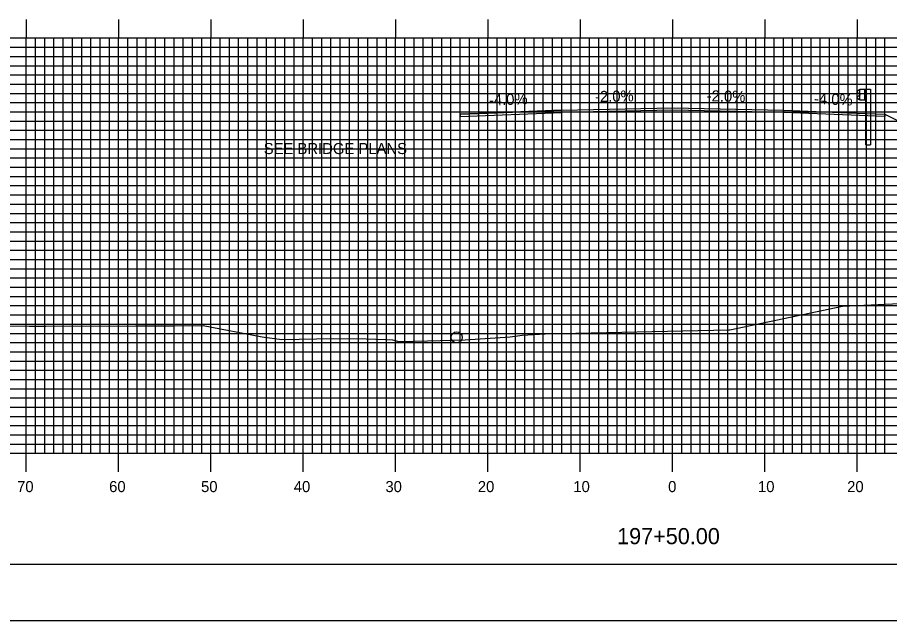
# Model space of a CAD drawing. Extents: x 1790124 to 1790467, y 442591 to 442811.
# Drawn here: x 1790218.7 to 1790313.2, y 442590.5 to 442655.9 of the extents above; entities that cross this region are included whole.
import ezdxf

# ---------------------------------------------------------------- set-up
doc = ezdxf.new("R2010")
doc.units = 0
for name, color, linetype in [('ANNOTATION', 7, 'Continuous'), ('BORDER', 7, 'Continuous'), ('D_Guardrail_Beam_Rt', 7, 'Continuous'), ('D_Roadway_Centerline', 7, 'Continuous'), ('D_Roadway_Edge_Shoulder', 7, 'Continuous'), ('D_Roadway_Edge_TW', 7, 'Continuous'), ('H_V ANNOTATION', 7, 'Continuous'), ('MAJOR', 7, 'Continuous'), ('MINOR', 7, 'Continuous'), ('PLOT BOUNDARY', 7, 'Continuous'), ('S_Drainage_Invert', 7, 'Continuous'), ('S_Roadway_Centerline', 7, 'Continuous')]:
    doc.layers.add(name, color=color, linetype=linetype)

msp = doc.modelspace()

# ---------------------------------------------------------------- linework, layer by layer
at = {"layer": 'ANNOTATION'}
msp.add_line((1790312.696, 442645.402), (1790350.545, 442626.478), dxfattribs=at)
at = {"layer": 'BORDER'}
msp.add_lwpolyline([(1790140.096, 442596.665), (1790460.096, 442596.665), (1790460.096, 442806.665), (1790140.096, 442806.665)], close=True, dxfattribs=at)
at = {"layer": 'D_Guardrail_Beam_Rt'}
for p, q in [((1790309.967, 442648.106), (1790310.654, 442648.106)), ((1790309.967, 442646.939), (1790309.967, 442648.106)), ((1790310.487, 442648.106), (1790310.487, 442646.939)), ((1790310.592, 442648.106), (1790310.592, 442646.939)), ((1790310.654, 442648.106), (1790311.125, 442648.106)), ((1790310.654, 442648.106), (1790310.654, 442646.939)), ((1790311.125, 442648.106), (1790311.125, 442642.106)), ((1790309.877, 442648.001), (1790309.733, 442647.901)), ((1790309.733, 442647.758), (1790309.929, 442647.622)), ((1790309.929, 442647.423), (1790309.733, 442647.287)), ((1790309.733, 442647.144), (1790309.877, 442647.044)), ((1790309.967, 442648.022), (1790309.892, 442648.008)), ((1790309.962, 442647.558), (1790309.962, 442647.487)), ((1790309.892, 442647.037), (1790309.967, 442647.022)), ((1790310.654, 442646.939), (1790309.967, 442646.939)), ((1790310.633, 442642.106), (1790310.633, 442646.939)), ((1790310.633, 442642.106), (1790311.125, 442642.106))]:
    msp.add_line(p, q, dxfattribs=at)
for centre, major_axis, start_param, end_param in [((1790309.783, 442647.83), (-0.0877, 0), 5.323254, 7.243116), ((1790309.783, 442647.215), (-0.0877, 0), 5.323254, 7.243116), ((1790309.901, 442647.967), (-0.0417, 0), 4.907132, 5.323254), ((1790309.883, 442647.558), (0.0789, 0), 0, 0.959931), ((1790309.883, 442647.487), (0.0789, 0), 5.323254, 6.283185), ((1790309.901, 442647.078), (-0.0417, 0), 0.959931, 1.376053)]:
    msp.add_ellipse(centre, major_axis=major_axis, ratio=0.995501, start_param=start_param, end_param=end_param, dxfattribs=at)
at = {"layer": 'D_Roadway_Centerline'}
msp.add_lwpolyline([(1790266.696, 442645.402), (1790269.696, 442645.522), (1790277.696, 442645.842), (1790289.696, 442646.082), (1790301.696, 442645.842), (1790309.696, 442645.522), (1790312.696, 442645.402)], dxfattribs=at)
at = {"layer": 'D_Roadway_Edge_Shoulder'}
for points in [[(1790277.696, 442645.842), (1790269.696, 442645.522), (1790269.696, 442645.522), (1790266.696, 442645.402), (1790266.696, 442645.152), (1790277.696, 442645.592)], [(1790301.696, 442645.842), (1790309.696, 442645.522), (1790309.696, 442645.522), (1790312.696, 442645.402), (1790312.696, 442645.152), (1790301.696, 442645.592)]]:
    msp.add_lwpolyline(points, close=True, dxfattribs=at)
at = {"layer": 'D_Roadway_Edge_TW'}
msp.add_lwpolyline([(1790277.696, 442645.592), (1790277.696, 442645.842), (1790289.696, 442646.082), (1790301.696, 442645.842), (1790301.696, 442645.592), (1790289.696, 442645.832)], close=True, dxfattribs=at)
at = {"layer": 'MAJOR'}
for p, q in [((1790219.696, 442655.669), (1790219.696, 442653.665)), ((1790229.696, 442655.669), (1790229.696, 442653.665)), ((1790239.696, 442655.669), (1790239.696, 442653.665)), ((1790249.696, 442655.669), (1790249.696, 442653.665)), ((1790259.696, 442655.669), (1790259.696, 442653.665)), ((1790269.696, 442655.669), (1790269.696, 442653.665)), ((1790279.696, 442655.669), (1790279.696, 442653.665)), ((1790289.696, 442655.669), (1790289.696, 442653.665)), ((1790299.696, 442655.669), (1790299.696, 442653.665)), ((1790309.696, 442655.669), (1790309.696, 442653.665)), ((1790149.696, 442653.665), (1790429.696, 442653.665)), ((1790149.696, 442653.665), (1790429.696, 442653.665)), ((1790219.696, 442608.665), (1790219.696, 442653.665)), ((1790229.696, 442608.665), (1790229.696, 442653.665)), ((1790239.696, 442608.665), (1790239.696, 442653.665)), ((1790249.696, 442608.665), (1790249.696, 442653.665)), ((1790259.696, 442608.665), (1790259.696, 442653.665)), ((1790269.696, 442608.665), (1790269.696, 442653.665)), ((1790279.696, 442608.665), (1790279.696, 442653.665)), ((1790289.696, 442608.665), (1790289.696, 442653.665)), ((1790299.696, 442608.665), (1790299.696, 442653.665)), ((1790309.696, 442608.665), (1790309.696, 442653.665)), ((1790149.696, 442648.665), (1790429.696, 442648.665)), ((1790149.696, 442643.665), (1790429.696, 442643.665)), ((1790149.696, 442638.665), (1790429.696, 442638.665)), ((1790149.696, 442633.665), (1790429.696, 442633.665)), ((1790149.696, 442628.665), (1790429.696, 442628.665)), ((1790149.696, 442623.665), (1790429.696, 442623.665)), ((1790149.696, 442618.665), (1790429.696, 442618.665)), ((1790149.696, 442613.665), (1790429.696, 442613.665)), ((1790149.696, 442608.665), (1790429.696, 442608.665)), ((1790149.696, 442608.665), (1790429.696, 442608.665)), ((1790219.696, 442606.661), (1790219.696, 442608.665)), ((1790229.696, 442606.661), (1790229.696, 442608.665)), ((1790239.696, 442606.661), (1790239.696, 442608.665)), ((1790249.696, 442606.661), (1790249.696, 442608.665)), ((1790259.696, 442606.661), (1790259.696, 442608.665)), ((1790269.696, 442606.661), (1790269.696, 442608.665)), ((1790279.696, 442606.661), (1790279.696, 442608.665)), ((1790289.696, 442606.661), (1790289.696, 442608.665)), ((1790299.696, 442606.661), (1790299.696, 442608.665)), ((1790309.696, 442606.661), (1790309.696, 442608.665))]:
    msp.add_line(p, q, dxfattribs=at)
at = {"layer": 'MINOR'}
for p, q in [((1790220.696, 442608.665), (1790220.696, 442653.665)), ((1790221.696, 442608.665), (1790221.696, 442653.665)), ((1790222.696, 442608.665), (1790222.696, 442653.665)), ((1790223.696, 442608.665), (1790223.696, 442653.665)), ((1790224.696, 442608.665), (1790224.696, 442653.665)), ((1790225.696, 442608.665), (1790225.696, 442653.665)), ((1790226.696, 442608.665), (1790226.696, 442653.665)), ((1790227.696, 442608.665), (1790227.696, 442653.665)), ((1790228.696, 442608.665), (1790228.696, 442653.665)), ((1790230.696, 442608.665), (1790230.696, 442653.665)), ((1790231.696, 442608.665), (1790231.696, 442653.665)), ((1790232.696, 442608.665), (1790232.696, 442653.665)), ((1790233.696, 442608.665), (1790233.696, 442653.665)), ((1790234.696, 442608.665), (1790234.696, 442653.665)), ((1790235.696, 442608.665), (1790235.696, 442653.665)), ((1790236.696, 442608.665), (1790236.696, 442653.665)), ((1790237.696, 442608.665), (1790237.696, 442653.665)), ((1790238.696, 442608.665), (1790238.696, 442653.665)), ((1790240.696, 442608.665), (1790240.696, 442653.665)), ((1790241.696, 442608.665), (1790241.696, 442653.665)), ((1790242.696, 442608.665), (1790242.696, 442653.665)), ((1790243.696, 442608.665), (1790243.696, 442653.665)), ((1790244.696, 442608.665), (1790244.696, 442653.665)), ((1790245.696, 442608.665), (1790245.696, 442653.665)), ((1790246.696, 442608.665), (1790246.696, 442653.665)), ((1790247.696, 442608.665), (1790247.696, 442653.665)), ((1790248.696, 442608.665), (1790248.696, 442653.665)), ((1790250.696, 442608.665), (1790250.696, 442653.665)), ((1790251.696, 442608.665), (1790251.696, 442653.665)), ((1790252.696, 442608.665), (1790252.696, 442653.665)), ((1790253.696, 442608.665), (1790253.696, 442653.665)), ((1790254.696, 442608.665), (1790254.696, 442653.665)), ((1790255.696, 442608.665), (1790255.696, 442653.665)), ((1790256.696, 442608.665), (1790256.696, 442653.665)), ((1790257.696, 442608.665), (1790257.696, 442653.665)), ((1790258.696, 442608.665), (1790258.696, 442653.665)), ((1790260.696, 442608.665), (1790260.696, 442653.665)), ((1790261.696, 442608.665), (1790261.696, 442653.665)), ((1790262.696, 442608.665), (1790262.696, 442653.665)), ((1790263.696, 442608.665), (1790263.696, 442653.665)), ((1790264.696, 442608.665), (1790264.696, 442653.665)), ((1790265.696, 442608.665), (1790265.696, 442653.665)), ((1790266.696, 442608.665), (1790266.696, 442653.665)), ((1790267.696, 442608.665), (1790267.696, 442653.665)), ((1790268.696, 442608.665), (1790268.696, 442653.665)), ((1790270.696, 442608.665), (1790270.696, 442653.665)), ((1790271.696, 442608.665), (1790271.696, 442653.665)), ((1790272.696, 442608.665), (1790272.696, 442653.665)), ((1790273.696, 442608.665), (1790273.696, 442653.665)), ((1790274.696, 442608.665), (1790274.696, 442653.665)), ((1790275.696, 442608.665), (1790275.696, 442653.665)), ((1790276.696, 442608.665), (1790276.696, 442653.665)), ((1790277.696, 442608.665), (1790277.696, 442653.665)), ((1790278.696, 442608.665), (1790278.696, 442653.665)), ((1790280.696, 442608.665), (1790280.696, 442653.665)), ((1790281.696, 442608.665), (1790281.696, 442653.665)), ((1790282.696, 442608.665), (1790282.696, 442653.665)), ((1790283.696, 442608.665), (1790283.696, 442653.665)), ((1790284.696, 442608.665), (1790284.696, 442653.665)), ((1790285.696, 442608.665), (1790285.696, 442653.665)), ((1790286.696, 442608.665), (1790286.696, 442653.665)), ((1790287.696, 442608.665), (1790287.696, 442653.665)), ((1790288.696, 442608.665), (1790288.696, 442653.665)), ((1790290.696, 442608.665), (1790290.696, 442653.665)), ((1790291.696, 442608.665), (1790291.696, 442653.665)), ((1790292.696, 442608.665), (1790292.696, 442653.665)), ((1790293.696, 442608.665), (1790293.696, 442653.665)), ((1790294.696, 442608.665), (1790294.696, 442653.665)), ((1790295.696, 442608.665), (1790295.696, 442653.665)), ((1790296.696, 442608.665), (1790296.696, 442653.665)), ((1790297.696, 442608.665), (1790297.696, 442653.665)), ((1790298.696, 442608.665), (1790298.696, 442653.665)), ((1790300.696, 442608.665), (1790300.696, 442653.665)), ((1790301.696, 442608.665), (1790301.696, 442653.665)), ((1790302.696, 442608.665), (1790302.696, 442653.665)), ((1790303.696, 442608.665), (1790303.696, 442653.665)), ((1790304.696, 442608.665), (1790304.696, 442653.665)), ((1790305.696, 442608.665), (1790305.696, 442653.665)), ((1790306.696, 442608.665), (1790306.696, 442653.665)), ((1790307.696, 442608.665), (1790307.696, 442653.665)), ((1790308.696, 442608.665), (1790308.696, 442653.665)), ((1790310.696, 442608.665), (1790310.696, 442653.665)), ((1790311.696, 442608.665), (1790311.696, 442653.665)), ((1790312.696, 442608.665), (1790312.696, 442653.665)), ((1790149.696, 442652.665), (1790429.696, 442652.665)), ((1790149.696, 442651.665), (1790429.696, 442651.665)), ((1790149.696, 442650.665), (1790429.696, 442650.665)), ((1790149.696, 442649.665), (1790429.696, 442649.665)), ((1790149.696, 442647.665), (1790429.696, 442647.665)), ((1790149.696, 442646.665), (1790429.696, 442646.665)), ((1790149.696, 442645.665), (1790429.696, 442645.665)), ((1790149.696, 442644.665), (1790429.696, 442644.665)), ((1790149.696, 442642.665), (1790429.696, 442642.665)), ((1790149.696, 442641.665), (1790429.696, 442641.665)), ((1790149.696, 442640.665), (1790429.696, 442640.665)), ((1790149.696, 442639.665), (1790429.696, 442639.665)), ((1790149.696, 442637.665), (1790429.696, 442637.665)), ((1790149.696, 442636.665), (1790429.696, 442636.665)), ((1790149.696, 442635.665), (1790429.696, 442635.665)), ((1790149.696, 442634.665), (1790429.696, 442634.665)), ((1790149.696, 442632.665), (1790429.696, 442632.665)), ((1790149.696, 442631.665), (1790429.696, 442631.665)), ((1790149.696, 442630.665), (1790429.696, 442630.665)), ((1790149.696, 442629.665), (1790429.696, 442629.665)), ((1790149.696, 442627.665), (1790429.696, 442627.665)), ((1790149.696, 442626.665), (1790429.696, 442626.665)), ((1790149.696, 442625.665), (1790429.696, 442625.665)), ((1790149.696, 442624.665), (1790429.696, 442624.665)), ((1790149.696, 442622.665), (1790429.696, 442622.665)), ((1790149.696, 442621.665), (1790429.696, 442621.665)), ((1790149.696, 442620.665), (1790429.696, 442620.665)), ((1790149.696, 442619.665), (1790429.696, 442619.665)), ((1790149.696, 442617.665), (1790429.696, 442617.665)), ((1790149.696, 442616.665), (1790429.696, 442616.665)), ((1790149.696, 442615.665), (1790429.696, 442615.665)), ((1790149.696, 442614.665), (1790429.696, 442614.665)), ((1790149.696, 442612.665), (1790429.696, 442612.665)), ((1790149.696, 442611.665), (1790429.696, 442611.665)), ((1790149.696, 442610.665), (1790429.696, 442610.665)), ((1790149.696, 442609.665), (1790429.696, 442609.665))]:
    msp.add_line(p, q, dxfattribs=at)
at = {"layer": 'PLOT BOUNDARY'}
msp.add_lwpolyline([(1790123.909, 442590.547), (1790463.909, 442590.547), (1790463.909, 442810.547), (1790123.909, 442810.547)], close=True, dxfattribs=at)
at = {"layer": 'S_Drainage_Invert'}
msp.add_circle((1790266.314, 442621.224), 0.6, dxfattribs=at)
at = {"layer": 'S_Roadway_Centerline'}
msp.add_lwpolyline([(1790215.748, 442622.512), (1790220.023, 442622.444), (1790221.826, 442622.443), (1790231.561, 442622.493), (1790235.657, 442622.479), (1790238.844, 442622.507), (1790245.239, 442621.269), (1790247.366, 442620.998), (1790253.016, 442621.096), (1790256.513, 442621.065), (1790258.603, 442621.006), (1790259.35, 442620.947), (1790260.059, 442620.799), (1790263.149, 442620.852), (1790267.219, 442620.97), (1790272.101, 442621.288), (1790273.419, 442621.46), (1790275.904, 442621.624), (1790295.804, 442622.028), (1790295.887, 442622.031), (1790308.086, 442624.593), (1790314.261, 442624.9)], dxfattribs=at)

# ---------------------------------------------------------------- texts
at = {"layer": 'ANNOTATION'}
for s, rotation, p in [('-4.0%', 2.29061, (1790269.828, 442646.329)), ('-2.0%', 1.14576, (1790281.302, 442646.715)), ('-2.0%', 358.85424, (1790293.382, 442646.809)), ('-4.0%', 357.70939, (1790304.988, 442646.512))]:
    msp.add_text(s, height=1.2, rotation=rotation, dxfattribs=at).set_placement(p)
msp.add_text('SEE BRIDGE PLANS', height=1.2, dxfattribs=at).set_placement((1790245.414, 442641.088))
at = {"layer": 'D_Roadway_Centerline'}
for s, p in [('C', (1790289.691, 442646.082)), ('L', (1790289.696, 442646.075))]:
    msp.add_text(s, height=0.0146, dxfattribs=at).set_placement(p)
at = {"layer": 'H_V ANNOTATION'}
for s, height, p in [('70', 1.2, (1790218.7, 442604.465)), ('60', 1.2, (1790228.668, 442604.465)), ('50', 1.2, (1790238.625, 442604.465)), ('40', 1.2, (1790248.668, 442604.465)), ('30', 1.2, (1790258.593, 442604.465)), ('20', 1.2, (1790268.604, 442604.465)), ('10', 1.2, (1790278.946, 442604.465)), ('0', 1.2, (1790289.214, 442604.465)), ('10', 1.2, (1790298.946, 442604.465)), ('20', 1.2, (1790308.604, 442604.465)), ('197+50.00', 1.75, (1790283.687, 442598.821))]:
    msp.add_text(s, height=height, dxfattribs=at).set_placement(p)

doc.saveas('drawing.dxf')
